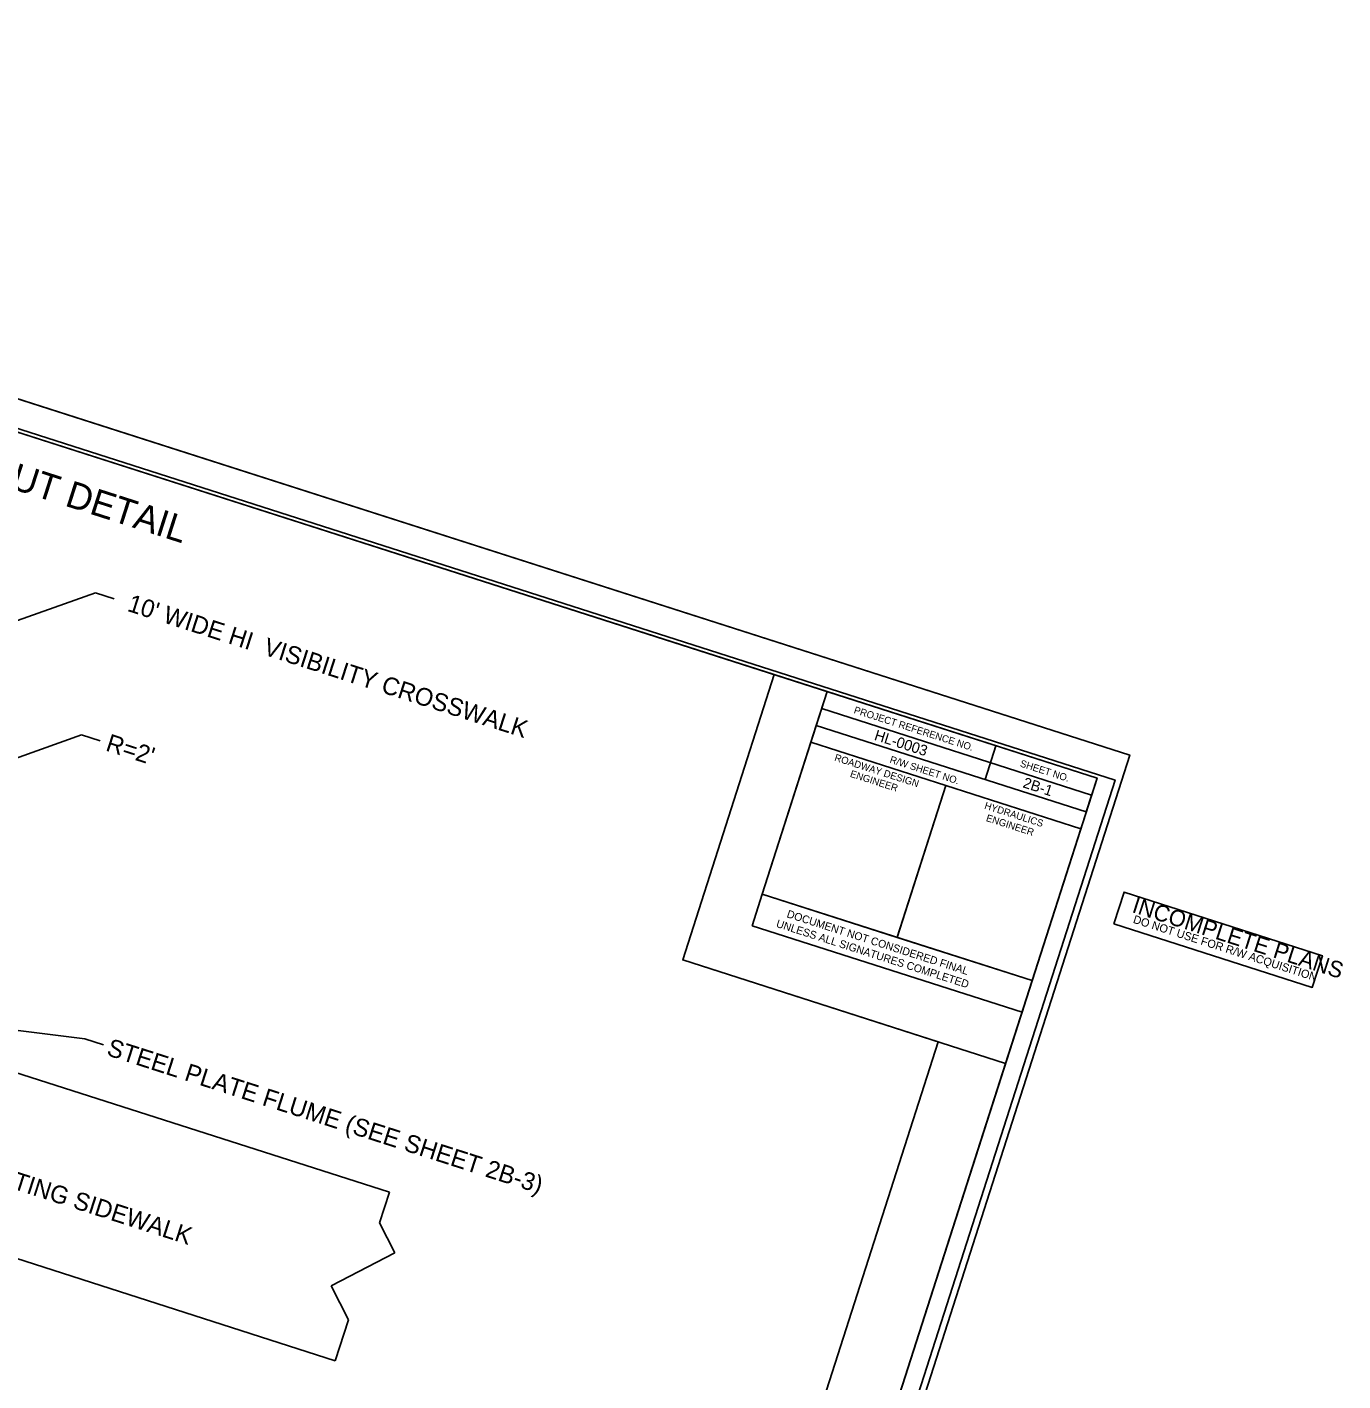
# Model space of a CAD drawing. Extents: x 928111 to 937215, y 684320 to 686530.
# Drawn here: x 933670.73 to 933707.86, y 684712.61 to 684750.83 of the extents above; entities that cross this region are included whole.
import ezdxf

# ---------------------------------------------------------------- set-up
doc = ezdxf.new("R2010")
doc.units = 0
for name, color, linetype in [('Exist Roads EOP', 7, 'Continuous'), ('Prop Dimension', 7, 'Continuous'), ('Prop DSN Text', 7, 'Continuous'), ('Sheet Clip Boundary CELL', 7, 'Continuous'), ('Sheet Cutting Line CELL', 7, 'Continuous'), ('Sheet Data Field CELL', 7, 'Continuous'), ('Sheet Layout Plan Border', 7, 'Continuous'), ('Sheet Plan CELL', 7, 'Continuous'), ('Sheet Plan Layout CELL', 7, 'Continuous'), ('Sheet Plot Border Inside CELL', 7, 'Continuous'), ('Sheet Plot Border Outside CELL', 7, 'Continuous'), ('Sheet Sticker Exception Certification CELL', 7, 'Continuous'), ('Sheet Sticker Incomplete CELL', 7, 'Continuous')]:
    doc.layers.add(name, color=color, linetype=linetype)

msp = doc.modelspace()

# ---------------------------------------------------------------- linework, layer by layer
at = {"layer": 'Exist Roads EOP'}
for p, q in [((933666.75, 684722.492), (933680.951, 684717.94)), ((933665.223, 684717.731), (933679.425, 684713.179)), ((933680.951, 684717.94), (933680.672, 684717.07)), ((933680.672, 684717.07), (933681.107, 684716.226)), ((933681.107, 684716.226), (933679.304, 684715.298)), ((933679.304, 684715.298), (933679.797, 684714.34)), ((933679.797, 684714.34), (933679.425, 684713.179))]:
    msp.add_line(p, q, dxfattribs=at)
at = {"layer": 'Prop Dimension'}
for p, q in [((933668.606, 684733.422), (933672.653, 684734.861)), ((933673.182, 684734.691), (933672.653, 684734.861)), ((933668.213, 684729.41), (933672.26, 684730.849)), ((933672.789, 684730.679), (933672.26, 684730.849)), ((933666.895, 684722.947), (933672.353, 684722.265)), ((933672.882, 684722.096), (933672.353, 684722.265))]:
    msp.add_line(p, q, dxfattribs=at)
at = {"layer": 'Sheet Clip Boundary CELL'}
msp.add_lwpolyline([(933632.873, 684707.339), (933686.201, 684690.246), (933696.439, 684722.185), (933689.23, 684724.496), (933691.812, 684732.552), (933645.693, 684747.335)], close=True, dxfattribs=at)
at = {"layer": 'Sheet Cutting Line CELL'}
msp.add_line((933701.848, 684730.28), (933637.722, 684750.835), dxfattribs=at)
at = {"layer": 'Sheet Layout Plan Border'}
msp.add_lwpolyline([(933632.873, 684707.339), (933686.201, 684690.246), (933696.439, 684722.185), (933689.23, 684724.496), (933691.812, 684732.552), (933645.693, 684747.335)], close=True, dxfattribs=at)
at = {"layer": 'Sheet Plan CELL'}
for p, q in [((933693.152, 684731.596), (933700.772, 684729.153)), ((933692.999, 684731.118), (933692.847, 684730.642)), ((933692.999, 684731.118), (933700.619, 684728.677)), ((933692.999, 684731.118), (933700.619, 684728.677)), ((933698.067, 684730.545), (933697.763, 684729.592)), ((933696.658, 684729.421), (933695.285, 684725.137))]:
    msp.add_line(p, q, dxfattribs=at)
for points in [[(933700.927, 684729.63), (933643.789, 684747.945), (933630.969, 684707.95), (933688.106, 684689.635)], [(933630.969, 684707.95), (933643.787, 684747.945), (933693.306, 684732.074), (933691.474, 684726.358), (933699.093, 684723.915), (933688.106, 684689.635)], [(933693.306, 684732.074), (933700.927, 684729.63), (933700.619, 684728.677), (933692.999, 684731.118)], [(933692.847, 684730.642), (933696.658, 684729.421), (933695.284, 684725.135), (933691.474, 684726.358)], [(933696.658, 684729.421), (933700.467, 684728.201), (933699.093, 684723.915), (933695.284, 684725.135)]]:
    msp.add_lwpolyline(points, close=True, dxfattribs=at)
at = {"layer": 'Sheet Plan Layout CELL'}
for points in [[(933643.787, 684747.945), (933630.969, 684707.95), (933688.105, 684689.635), (933698.343, 684721.575), (933689.23, 684724.496), (933691.812, 684732.552)], [(933689.23, 684724.496), (933698.344, 684721.575), (933700.927, 684729.63), (933691.812, 684732.552)]]:
    msp.add_lwpolyline(points, close=True, dxfattribs=at)
at = {"layer": 'Sheet Plot Border Inside CELL'}
msp.add_lwpolyline([(933625.091, 684709.728), (933688.551, 684689.388), (933701.432, 684729.573), (933637.973, 684749.914)], close=True, dxfattribs=at)
at = {"layer": 'Sheet Plot Border Outside CELL'}
msp.add_lwpolyline([(933624.352, 684709.125), (933688.478, 684688.57), (933701.848, 684730.28), (933637.722, 684750.835)], close=True, dxfattribs=at)
at = {"layer": 'Sheet Sticker Exception Certification CELL'}
for p, q in [((933691.187, 684725.462), (933691.474, 684726.358)), ((933691.187, 684725.462), (933691.474, 684726.358)), ((933691.474, 684726.358), (933699.094, 684723.915)), ((933691.474, 684726.358), (933699.094, 684723.915)), ((933698.807, 684723.02), (933691.187, 684725.462)), ((933698.807, 684723.02), (933691.187, 684725.462)), ((933699.093, 684723.915), (933698.807, 684723.02)), ((933699.093, 684723.915), (933698.807, 684723.02))]:
    msp.add_line(p, q, dxfattribs=at)
at = {"layer": 'Sheet Sticker Incomplete CELL'}
msp.add_lwpolyline([(933701.401, 684725.517), (933701.688, 684726.412), (933707.287, 684724.617), (933707, 684723.722)], close=True, dxfattribs=at)

# ---------------------------------------------------------------- texts
at = {"layer": 'Prop DSN Text'}
for s, height, p in [('PEDESTRIAN BULBOUT DETAIL ', 0.75, (933660.619, 684740.9)), ("10' WIDE HI  VISIBILITY CROSSWALK", 0.5, (933673.527, 684734.356)), ("R=2'", 0.5, (933672.917, 684730.414)), ('STEEL PLATE FLUME (SEE SHEET 2B-3)', 0.5, (933672.944, 684721.814)), ('EXISTING SIDEWALK ', 0.5, (933668.841, 684718.51))]:
    msp.add_text(s, height=height, rotation=342.2273, dxfattribs=at).set_placement(p)
at = {"layer": 'Sheet Data Field CELL'}
for s, p in [('HL-0003', (933694.616, 684730.716)), ('2B-1', (933698.809, 684729.375))]:
    msp.add_text(s, height=0.3, rotation=342.2273, dxfattribs=at).set_placement(p)
at = {"layer": 'Sheet Plan CELL'}
for s, p in [('PROJECT REFERENCE NO.', (933694.045, 684731.47)), ('ROADWAY DESIGN', (933693.496, 684730.128)), ('R/W SHEET NO.', (933695.058, 684730.072)), ('SHEET NO.', (933698.735, 684729.962)), ('ENGINEER', (933693.937, 684729.67)), ('HYDRAULICS', (933697.729, 684728.772)), ('ENGINEER', (933697.776, 684728.423))]:
    msp.add_text(s, height=0.2, rotation=342.2273, dxfattribs=at).set_placement(p)
at = {"layer": 'Sheet Sticker Exception Certification CELL'}
for s, p in [('DOCUMENT NOT CONSIDERED FINAL', (933692.15, 684725.706)), ('DOCUMENT NOT CONSIDERED FINAL', (933692.15, 684725.706)), ('UNLESS ALL SIGNATURES COMPLETED', (933691.85, 684725.433)), ('UNLESS ALL SIGNATURES COMPLETED', (933691.85, 684725.433))]:
    msp.add_text(s, height=0.22, rotation=342.2273, dxfattribs=at).set_placement(p)
at = {"layer": 'Sheet Sticker Incomplete CELL'}
for s, height, p in [('INCOMPLETE PLANS', 0.4608, (933701.885, 684725.853)), ('DO NOT USE FOR R/W ACQUISITION', 0.2304, (933701.924, 684725.549))]:
    msp.add_text(s, height=height, rotation=342.2273, dxfattribs=at).set_placement(p)

doc.saveas('drawing.dxf')
